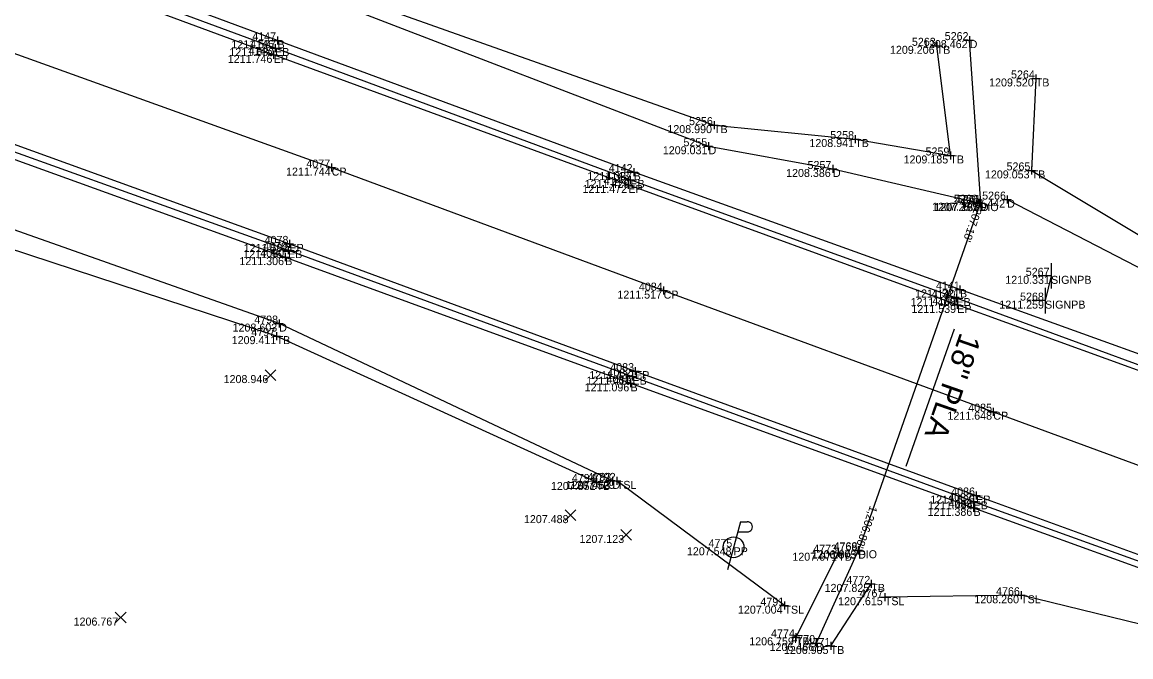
# Model space of a CAD drawing. Extents: x 2044996 to 2050343, y 455232 to 458054.
# Drawn here: x 2048212.4 to 2048351, y 456708.6 to 456787.9 of the extents above; entities that cross this region are included whole.
import ezdxf

# ---------------------------------------------------------------- set-up
doc = ezdxf.new("R2010")
doc.units = 0
for name, color, linetype in [('Default', 7, 'Continuous'), ('DR_X_Ditch', 7, 'Continuous'), ('DR_X_Elev_Flow', 7, 'Continuous'), ('DR_X_Storm_Sewer', 7, 'Continuous'), ('DR_X_Text', 7, 'Continuous'), ('DT_X_Contour_Minor', 7, 'Continuous'), ('DT_X_Contour_Text', 7, 'Continuous'), ('DT_X_Spot_Elev', 7, 'Continuous'), ('DT_X_Triangles', 7, 'Continuous'), ('DT_X_Void', 7, 'Continuous'), ('PV_X_COP', 7, 'Continuous'), ('PV_X_EOP', 7, 'Continuous'), ('PV_X_Shoulder_Aggregate', 7, 'Continuous'), ('SC_Scratch1', 7, 'Continuous'), ('SN_X_Public', 7, 'Continuous'), ('SV_X_Break_Lines', 7, 'Continuous'), ('SV_X_Toe_of_Slope', 7, 'Continuous'), ('SV_X_Top_of_Bank', 7, 'Continuous'), ('UT_X_Electric_Cells', 7, 'Continuous')]:
    doc.layers.add(name, color=color, linetype=linetype)

msp = doc.modelspace()

# ---------------------------------------------------------------- linework, layer by layer
at = {"layer": 'Default'}
msp.add_lwpolyline([(2048341.03, 456756.21), (2048340.28, 456753.11)], dxfattribs=at)
at = {"layer": 'DR_X_Ditch'}
for points in [[(2047780.51, 456960.13), (2047826.93, 456942.06), (2047870.38, 456926.94), (2047917.77, 456909.91), (2047942.94, 456900.89), (2047986.92, 456884.17), (2048032.77, 456867.49), (2048075.71, 456852.37), (2048118.48, 456836.63), (2048162.27, 456821), (2048204.38, 456806.34), (2048252.02, 456790.17), (2048298.22, 456772.41), (2048313.77, 456769.57), (2048332, 456765.35)], [(2048286.21, 456730.57), (2048244.57, 456750.24), (2048196.78, 456767.13), (2048157.76, 456781.54), (2048113.45, 456797.91), (2048070.52, 456814.66)], [(2048332.26, 456765.31), (2048330.86, 456785.68)], [(2048335.55, 456765.74), (2048373.99, 456745.88), (2048418.01, 456728.27), (2048467.59, 456710.52), (2048510.97, 456693.84), (2048561.78, 456674.87), (2048608.72, 456657.51)], [(2048316.94, 456721.85), (2048311.69, 456710.3)]]:
    msp.add_lwpolyline(points, dxfattribs=at)
at = {"layer": 'DR_X_Elev_Flow'}
for p, q in [((2048331.68, 456765.3), (2048332.68, 456765.3)), ((2048332.18, 456765.8), (2048332.18, 456764.8)), ((2048332.18, 456765.3), (2048332.18, 456765.3)), ((2048316.48, 456721.9), (2048317.48, 456721.9)), ((2048316.98, 456722.4), (2048316.98, 456721.4)), ((2048316.98, 456721.9), (2048316.98, 456721.9))]:
    msp.add_line(p, q, dxfattribs=at)
at = {"layer": 'DR_X_Storm_Sewer'}
msp.add_line((2048332.18, 456765.3), (2048316.98, 456721.9), dxfattribs=at)
at = {"layer": 'DR_X_Text'}
msp.add_line((2048322.94, 456732.4), (2048328.96, 456749.6), dxfattribs=at)
at = {"layer": 'DT_X_Spot_Elev'}
for p, q in [((2048242.8, 456743.14), (2048244.13, 456744.47)), ((2048242.8, 456744.47), (2048244.13, 456743.14)), ((2048280.32, 456725.62), (2048281.65, 456726.95)), ((2048280.32, 456726.95), (2048281.65, 456725.62)), ((2048287.26, 456723.15), (2048288.59, 456724.48)), ((2048287.26, 456724.48), (2048288.59, 456723.15)), ((2048224.08, 456712.82), (2048225.42, 456714.15)), ((2048224.08, 456714.15), (2048225.42, 456712.82))]:
    msp.add_line(p, q, dxfattribs=at)
at = {"layer": 'DT_X_Void'}
for p, q in [((2048243.86, 456785.65), (2048244.86, 456785.65)), ((2048244.36, 456786.15), (2048244.36, 456785.15)), ((2048244.36, 456785.65), (2048244.36, 456785.65)), ((2048330.36, 456785.68), (2048331.36, 456785.68)), ((2048330.86, 456786.18), (2048330.86, 456785.18)), ((2048330.86, 456785.68), (2048330.86, 456785.68)), ((2048243.56, 456784.69), (2048244.56, 456784.69)), ((2048243.87, 456784.34), (2048243.87, 456783.34)), ((2048244.06, 456785.19), (2048244.06, 456784.19)), ((2048244.06, 456784.69), (2048244.06, 456784.69)), ((2048326.24, 456784.97), (2048327.24, 456784.97)), ((2048326.74, 456785.47), (2048326.74, 456784.47)), ((2048326.74, 456784.97), (2048326.74, 456784.97)), ((2048243.37, 456783.84), (2048244.37, 456783.84)), ((2048243.87, 456783.84), (2048243.87, 456783.84)), ((2048338.62, 456780.89), (2048339.62, 456780.89)), ((2048339.12, 456781.39), (2048339.12, 456780.39)), ((2048339.12, 456780.89), (2048339.12, 456780.89)), ((2048298.41, 456775.05), (2048299.41, 456775.05)), ((2048298.91, 456775.55), (2048298.91, 456774.55)), ((2048298.91, 456775.05), (2048298.91, 456775.05)), ((2048316.05, 456773.31), (2048317.05, 456773.31)), ((2048316.55, 456773.81), (2048316.55, 456772.81)), ((2048316.55, 456773.31), (2048316.55, 456773.31)), ((2048297.72, 456772.41), (2048298.72, 456772.41)), ((2048298.22, 456772.91), (2048298.22, 456771.91)), ((2048298.22, 456772.41), (2048298.22, 456772.41)), ((2048328.45, 456771.76), (2048328.45, 456770.76)), ((2048327.95, 456771.26), (2048328.95, 456771.26)), ((2048328.45, 456771.26), (2048328.45, 456771.26)), ((2048250.62, 456769.74), (2048251.62, 456769.74)), ((2048251.12, 456770.24), (2048251.12, 456769.24)), ((2048251.12, 456769.74), (2048251.12, 456769.74)), ((2048288.37, 456769.18), (2048289.37, 456769.18)), ((2048288.87, 456769.68), (2048288.87, 456768.68)), ((2048288.87, 456769.18), (2048288.87, 456769.18)), ((2048313.27, 456769.57), (2048314.27, 456769.57)), ((2048313.77, 456770.07), (2048313.77, 456769.07)), ((2048313.77, 456769.57), (2048313.77, 456769.57)), ((2048338.1, 456769.39), (2048339.1, 456769.39)), ((2048338.6, 456769.89), (2048338.6, 456768.89)), ((2048338.6, 456769.39), (2048338.6, 456769.39)), ((2048287.7, 456767.58), (2048288.7, 456767.58)), ((2048287.95, 456768.21), (2048288.95, 456768.21)), ((2048288.2, 456768.08), (2048288.2, 456767.08)), ((2048288.2, 456767.58), (2048288.2, 456767.58)), ((2048288.45, 456768.71), (2048288.45, 456767.71)), ((2048288.45, 456768.21), (2048288.45, 456768.21)), ((2048335.55, 456766.24), (2048335.55, 456765.24)), ((2048331.5, 456765.35), (2048332.5, 456765.35)), ((2048331.76, 456765.31), (2048332.76, 456765.31)), ((2048332, 456765.85), (2048332, 456764.85)), ((2048332, 456765.35), (2048332, 456765.35)), ((2048332.26, 456765.81), (2048332.26, 456764.81)), ((2048332.26, 456765.31), (2048332.26, 456765.31)), ((2048335.05, 456765.74), (2048336.05, 456765.74)), ((2048335.55, 456765.74), (2048335.55, 456765.74)), ((2048245.85, 456760.7), (2048245.85, 456759.7)), ((2048245.17, 456759.42), (2048246.17, 456759.42)), ((2048245.35, 456760.2), (2048246.35, 456760.2)), ((2048245.67, 456759.92), (2048245.67, 456758.92)), ((2048245.67, 456759.42), (2048245.67, 456759.42)), ((2048245.85, 456760.2), (2048245.85, 456760.2)), ((2048244.82, 456758.55), (2048245.82, 456758.55)), ((2048245.32, 456759.05), (2048245.32, 456758.05)), ((2048245.32, 456758.55), (2048245.32, 456758.55)), ((2048292.11, 456754.36), (2048293.11, 456754.36)), ((2048292.61, 456754.86), (2048292.61, 456753.86)), ((2048292.61, 456754.36), (2048292.61, 456754.36)), ((2048329.15, 456754.5), (2048330.15, 456754.5)), ((2048329.21, 456753.93), (2048329.21, 456752.93)), ((2048329.65, 456755), (2048329.65, 456754)), ((2048329.65, 456754.5), (2048329.65, 456754.5)), ((2048328.71, 456753.43), (2048329.71, 456753.43)), ((2048328.8, 456752.57), (2048329.8, 456752.57)), ((2048329.21, 456753.43), (2048329.21, 456753.43)), ((2048329.3, 456753.07), (2048329.3, 456752.07)), ((2048329.3, 456752.57), (2048329.3, 456752.57)), ((2048244.07, 456750.24), (2048245.07, 456750.24)), ((2048244.57, 456750.74), (2048244.57, 456749.74)), ((2048244.57, 456750.24), (2048244.57, 456750.24)), ((2048243.74, 456748.67), (2048244.74, 456748.67)), ((2048244.24, 456749.17), (2048244.24, 456748.17)), ((2048244.24, 456748.67), (2048244.24, 456748.67)), ((2048288.55, 456744.29), (2048289.55, 456744.29)), ((2048288.72, 456744.11), (2048288.72, 456743.11)), ((2048289.05, 456744.79), (2048289.05, 456743.79)), ((2048289.05, 456744.29), (2048289.05, 456744.29)), ((2048287.98, 456742.77), (2048288.98, 456742.77)), ((2048288.22, 456743.61), (2048289.22, 456743.61)), ((2048288.48, 456743.27), (2048288.48, 456742.27)), ((2048288.48, 456742.77), (2048288.48, 456742.77)), ((2048288.72, 456743.61), (2048288.72, 456743.61)), ((2048333.31, 456739.22), (2048334.31, 456739.22)), ((2048333.81, 456739.72), (2048333.81, 456738.72)), ((2048333.81, 456739.22), (2048333.81, 456739.22)), ((2048283.73, 456730.43), (2048284.73, 456730.43)), ((2048284.23, 456730.93), (2048284.23, 456729.93)), ((2048284.23, 456730.43), (2048284.23, 456730.43)), ((2048285.71, 456730.57), (2048286.71, 456730.57)), ((2048286.21, 456731.07), (2048286.21, 456730.07)), ((2048286.21, 456730.57), (2048286.21, 456730.57)), ((2048286.26, 456730.57), (2048287.26, 456730.57)), ((2048286.76, 456731.07), (2048286.76, 456730.07)), ((2048286.76, 456730.57), (2048286.76, 456730.57)), ((2048331.67, 456729.24), (2048331.67, 456728.24)), ((2048330.85, 456728.01), (2048331.85, 456728.01)), ((2048331.17, 456728.74), (2048332.17, 456728.74)), ((2048331.35, 456728.51), (2048331.35, 456727.51)), ((2048331.35, 456728.01), (2048331.35, 456728.01)), ((2048331.35, 456727.7), (2048331.35, 456726.7)), ((2048331.67, 456728.74), (2048331.67, 456728.74)), ((2048330.85, 456727.2), (2048331.85, 456727.2)), ((2048331.35, 456727.2), (2048331.35, 456727.2)), ((2048314.42, 456722.09), (2048314.42, 456721.09)), ((2048316.44, 456721.85), (2048317.44, 456721.85)), ((2048316.94, 456722.35), (2048316.94, 456721.35)), ((2048316.94, 456721.85), (2048316.94, 456721.85)), ((2048313.92, 456721.59), (2048314.92, 456721.59)), ((2048314.42, 456721.59), (2048314.42, 456721.59)), ((2048318.57, 456718.19), (2048318.57, 456717.19)), ((2048318.07, 456717.69), (2048319.07, 456717.69)), ((2048318.57, 456717.69), (2048318.57, 456717.69)), ((2048320.26, 456716.53), (2048320.26, 456715.53)), ((2048337.28, 456716.77), (2048337.28, 456715.77)), ((2048307.21, 456714.97), (2048308.21, 456714.97)), ((2048307.71, 456715.47), (2048307.71, 456714.47)), ((2048307.71, 456714.97), (2048307.71, 456714.97)), ((2048319.76, 456716.03), (2048320.76, 456716.03)), ((2048320.26, 456716.03), (2048320.26, 456716.03)), ((2048336.78, 456716.27), (2048337.78, 456716.27)), ((2048337.28, 456716.27), (2048337.28, 456716.27)), ((2048308.63, 456711.01), (2048309.63, 456711.01)), ((2048309.13, 456711.51), (2048309.13, 456710.51)), ((2048309.13, 456711.01), (2048309.13, 456711.01)), ((2048311.69, 456710.8), (2048311.69, 456709.8)), ((2048311.19, 456710.3), (2048312.19, 456710.3)), ((2048311.69, 456710.3), (2048311.69, 456710.3)), ((2048312.99, 456709.93), (2048313.99, 456709.93)), ((2048313.49, 456710.43), (2048313.49, 456709.43)), ((2048313.49, 456709.93), (2048313.49, 456709.93))]:
    msp.add_line(p, q, dxfattribs=at)
at = {"layer": 'PV_X_COP'}
msp.add_lwpolyline([(2047721.58, 456961.45), (2047764.11, 456945.53), (2047805.42, 456930.56), (2047848.07, 456915.19), (2047886.38, 456901.23), (2047928.53, 456886.16), (2047967.24, 456872.35), (2048004.2, 456859.18), (2048043.3, 456845.25), (2048086.02, 456829.64), (2048125.99, 456815.39), (2048168.62, 456799.78), (2048207.67, 456785.38), (2048251.12, 456769.74), (2048292.61, 456754.36), (2048333.81, 456739.22), (2048373.81, 456724.48), (2048417.09, 456709.08), (2048458.61, 456693.82), (2048498.86, 456678.79), (2048537.43, 456664.8), (2048579.13, 456649.5), (2048615.78, 456636.27)], dxfattribs=at)
at = {"layer": 'PV_X_EOP'}
for p, q in [((2048243.87, 456783.84), (2048200.13, 456800.03)), ((2048288.2, 456767.58), (2048243.87, 456783.84)), ((2048203.99, 456775.35), (2048245.85, 456760.2)), ((2048329.3, 456752.57), (2048288.2, 456767.58)), ((2048245.85, 456760.2), (2048289.05, 456744.29)), ((2048369.11, 456738.16), (2048329.3, 456752.57)), ((2048289.05, 456744.29), (2048331.67, 456728.74)), ((2048331.67, 456728.74), (2048371.07, 456714.38))]:
    msp.add_line(p, q, dxfattribs=at)
at = {"layer": 'PV_X_Shoulder_Aggregate'}
for points in [[(2048620.54, 456647.12), (2048583.12, 456660.67), (2048539.73, 456676.45), (2048498.23, 456691.52), (2048454.17, 456707.97), (2048410.24, 456724.1), (2048369.4, 456738.65), (2048329.21, 456753.43), (2048288.45, 456768.21), (2048244.06, 456784.69), (2048200.54, 456800.78), (2048154.81, 456817.47), (2048112.55, 456832.71), (2048067.31, 456849.18), (2048026.51, 456863.76), (2047982.25, 456879.67), (2047938.09, 456895.41), (2047894.6, 456910.89), (2047855.83, 456924.74), (2047813.34, 456939.9), (2047765.41, 456957.6), (2047718.77, 456974.89)], [(2048040.39, 456833.65), (2048080.57, 456819.36), (2048122.88, 456804.21), (2048163.75, 456789.21), (2048203.9, 456774.44), (2048245.67, 456759.42), (2048288.72, 456743.61), (2048331.35, 456728.01), (2048370.94, 456713.7), (2048413.11, 456698.36), (2048454.57, 456682.93), (2048494.04, 456668.41), (2048534.01, 456653.96), (2048574.84, 456639.09), (2048611.82, 456625.41)]]:
    msp.add_lwpolyline(points, dxfattribs=at)
at = {"layer": 'SN_X_Public'}
for p, q in [((2048341.03, 456757.81), (2048341.03, 456754.61)), ((2048341.03, 456756.21), (2048339.43, 456756.21)), ((2048340.28, 456754.71), (2048340.28, 456751.51)), ((2048340.28, 456753.11), (2048338.68, 456753.11))]:
    msp.add_line(p, q, dxfattribs=at)
at = {"layer": 'SV_X_Break_Lines'}
for points in [[(2048620.73, 456648.35), (2048583.39, 456661.98), (2048539.9, 456677.65), (2048498.37, 456692.73), (2048454.2, 456708.99), (2048410.48, 456724.96), (2048370.07, 456739.9), (2048329.65, 456754.5), (2048288.87, 456769.18), (2048244.36, 456785.65), (2048200.73, 456801.81), (2048154.72, 456818.61), (2048112.67, 456833.97), (2048067.63, 456850.21), (2048026.62, 456865.12), (2047982.64, 456881.49), (2047938.6, 456897.69), (2047895.04, 456913.55), (2047856.96, 456927.13), (2047813.61, 456942.44), (2047766.63, 456959.74), (2047718.99, 456976.33)], [(2047983.65, 456851.86), (2047998.98, 456847.09), (2048040.01, 456832.79), (2048080.02, 456818.41), (2048122.45, 456803.47), (2048163.47, 456788.33), (2048203.54, 456773.63), (2048245.32, 456758.55), (2048288.48, 456742.77), (2048331.35, 456727.2), (2048370.69, 456712.96), (2048412.95, 456697.59), (2048454.31, 456682.22), (2048493.85, 456667.9), (2048533.48, 456653.1), (2048574.57, 456638.27), (2048611.5, 456624.45)]]:
    msp.add_lwpolyline(points, dxfattribs=at)
at = {"layer": 'SV_X_Toe_of_Slope'}
for points in [[(2048307.71, 456714.97), (2048286.76, 456730.57)], [(2048404.84, 456696.78), (2048369.02, 456708.55), (2048337.28, 456716.27), (2048320.26, 456716.03)]]:
    msp.add_lwpolyline(points, dxfattribs=at)
at = {"layer": 'SV_X_Top_of_Bank'}
for points in [[(2047763.11, 456969.57), (2047782.88, 456962.79), (2047830.39, 456947.65), (2047873.41, 456931.98), (2047921.78, 456915.49), (2047944.39, 456907.04), (2047986.44, 456890.77), (2048035.77, 456871.04), (2048076.02, 456855.86), (2048121.82, 456840.13), (2048161.94, 456823.83), (2048204.58, 456808.51), (2048251.96, 456791.72), (2048298.91, 456775.05), (2048316.55, 456773.31), (2048328.45, 456771.26), (2048326.74, 456784.97)], [(2048284.23, 456730.43), (2048244.24, 456748.67), (2048196.38, 456764.37), (2048156.4, 456780.03), (2048112.39, 456796.2), (2048069.57, 456813.69)], [(2048339.12, 456780.89), (2048338.6, 456769.39), (2048375.24, 456747.38), (2048425.64, 456735.22), (2048467.88, 456719.52), (2048517.9, 456700.47), (2048561.92, 456683.71), (2048612.49, 456664.63)], [(2048314.42, 456721.59), (2048309.13, 456711.01)], [(2048313.49, 456709.93), (2048318.57, 456717.69)]]:
    msp.add_lwpolyline(points, dxfattribs=at)
at = {"layer": 'UT_X_Electric_Cells'}
for p, q in [((2048302.21, 456725.47), (2048300.6, 456719.47)), ((2048302.21, 456725.47), (2048303.06, 456725.47)), ((2048301.87, 456724.2), (2048303.06, 456724.2))]:
    msp.add_line(p, q, dxfattribs=at)
msp.add_circle((2048301.35, 456722.27), 1.3, dxfattribs=at)
msp.add_arc((2048303.07, 456724.83), 0.638, 268.8767, 91.1233, dxfattribs=at)

# ---------------------------------------------------------------- texts
at = {"layer": 'DR_X_Text'}
msp.add_text('18" PLA', height=2.8, rotation=250.7068, dxfattribs=at).set_placement((2048329.7, 456749.23))
at = {"layer": 'DT_X_Contour_Minor'}
for s, p in [('1211.577', (2048238.58, 456784.65)), ('1208.462', (2048325.02, 456784.68)), ('1211.680', (2048238.33, 456783.69)), ('1209.206', (2048320.9, 456783.97)), ('1211.746', (2048238.14, 456782.84)), ('1209.520', (2048333.29, 456779.89)), ('1208.990', (2048293.08, 456774.05)), ('1208.941', (2048310.83, 456772.31)), ('1209.031', (2048292.51, 456771.41)), ('1209.185', (2048322.6, 456770.26)), ('1211.744', (2048245.42, 456768.74)), ('1211.337', (2048283.09, 456768.18)), ('1208.386', (2048307.92, 456768.57)), ('1209.053', (2048332.77, 456768.39)), ('1211.472', (2048282.47, 456766.58)), ('1211.429', (2048282.74, 456767.21)), ('1207.250', (2048326.16, 456764.35)), ('1207.285', (2048326.41, 456764.31)), ('1207.181', (2048326.46, 456764.3)), ('1207.442', (2048329.71, 456764.74)), ('1211.561', (2048240.06, 456758.42)), ('1211.592', (2048240.13, 456759.2)), ('1211.306', (2048239.59, 456757.55)), ('1210.331', (2048335.31, 456755.21)), ('1211.517', (2048286.83, 456753.36)), ('1211.321', (2048324.04, 456753.5)), ('1211.460', (2048323.48, 456752.43)), ('1211.539', (2048323.58, 456751.57)), ('1211.259', (2048334.57, 456752.11)), ('1208.603', (2048238.74, 456749.24)), ('1209.411', (2048238.63, 456747.67)), ('1211.432', (2048283.32, 456743.29)), ('1208.946', (2048237.62, 456742.8)), ('1211.096', (2048282.74, 456741.77)), ('1211.415', (2048282.97, 456742.61)), ('1211.648', (2048328.08, 456738.22)), ('1207.851', (2048278.52, 456729.43)), ('1207.463', (2048280.38, 456729.57)), ('1207.529', (2048280.94, 456729.57)), ('1211.494', (2048325.65, 456727.01)), ('1211.526', (2048325.93, 456727.74)), ('1207.488', (2048275.15, 456725.29)), ('1211.386', (2048325.61, 456726.2)), ('1207.123', (2048282.1, 456722.81)), ('1207.548', (2048295.52, 456721.27)), ('1206.903', (2048311.11, 456720.85)), ('1206.875', (2048311.13, 456720.9)), ('1207.671', (2048308.7, 456720.59)), ('1207.825', (2048312.73, 456716.69)), ('1207.004', (2048301.9, 456713.97)), ('1207.615', (2048314.42, 456715.03)), ('1208.260', (2048331.45, 456715.27)), ('1206.767', (2048218.87, 456712.48)), ('1206.759', (2048303.31, 456710.01)), ('1206.466', (2048305.85, 456709.3)), ('1206.905', (2048307.64, 456708.93))]:
    msp.add_text(s, height=1, dxfattribs=at).set_placement(p)
at = {"layer": 'DT_X_Contour_Text'}
for s, p in [('B', (2048244.36, 456784.65)), ('D', (2048330.86, 456784.68)), ('EB', (2048244.06, 456783.69)), ('TB', (2048326.74, 456783.97)), ('EP', (2048243.87, 456782.84)), ('TB', (2048339.12, 456779.89)), ('TB', (2048298.91, 456774.05)), ('TB', (2048316.55, 456772.31)), ('D', (2048298.22, 456771.41)), ('TB', (2048328.45, 456770.26)), ('CP', (2048251.12, 456768.74)), ('B', (2048288.87, 456768.18)), ('D', (2048313.77, 456768.57)), ('TB', (2048338.6, 456768.39)), ('EP', (2048288.2, 456766.58)), ('EB', (2048288.45, 456767.21)), ('D', (2048332, 456764.35)), ('PIO', (2048332.18, 456764.3)), ('D', (2048332.26, 456764.31)), ('D', (2048335.55, 456764.74)), ('EB', (2048245.67, 456758.42)), ('EP', (2048245.85, 456759.2)), ('B', (2048245.32, 456757.55)), ('SIGNPB', (2048341.03, 456755.21)), ('CP', (2048292.61, 456753.36)), ('B', (2048329.65, 456753.5)), ('EB', (2048329.21, 456752.43)), ('EP', (2048329.3, 456751.57)), ('SIGNPB', (2048340.28, 456752.11)), ('D', (2048244.57, 456749.24)), ('TB', (2048244.24, 456747.67)), ('EP', (2048289.05, 456743.29)), ('B', (2048288.48, 456741.77)), ('EB', (2048288.72, 456742.61)), ('CP', (2048333.81, 456738.22)), ('TB', (2048284.23, 456729.43)), ('D', (2048286.21, 456729.57)), ('TSL', (2048286.76, 456729.57)), ('EB', (2048331.35, 456727.01)), ('EP', (2048331.67, 456727.74)), ('B', (2048331.35, 456726.2)), ('PP', (2048301.35, 456721.27)), ('D', (2048316.94, 456720.85)), ('PIO', (2048316.98, 456720.9)), ('TB', (2048314.42, 456720.59)), ('TB', (2048318.57, 456716.69)), ('TSL', (2048307.71, 456713.97)), ('TSL', (2048320.26, 456715.03)), ('TSL', (2048337.28, 456715.27)), ('TB', (2048309.13, 456710.01)), ('D', (2048311.69, 456709.3)), ('TB', (2048313.49, 456708.93))]:
    msp.add_text(s, height=1, dxfattribs=at).set_placement(p)
at = {"layer": 'DT_X_Triangles'}
for s, p in [('4146', (2048240.94, 456784.69)), ('4147', (2048241.2, 456785.65)), ('5263', (2048323.64, 456784.97)), ('5262', (2048327.74, 456785.68)), ('4145', (2048240.74, 456783.84)), ('5264', (2048336.03, 456780.89)), ('5256', (2048295.79, 456775.05)), ('5255', (2048295.09, 456772.41)), ('5258', (2048313.43, 456773.31)), ('5259', (2048325.35, 456771.26)), ('4077', (2048247.96, 456769.74)), ('5257', (2048310.6, 456769.57)), ('5265', (2048335.47, 456769.39)), ('4143', (2048285.34, 456768.21)), ('4142', (2048285.75, 456769.18)), ('4144', (2048285.11, 456767.58)), ('5260', (2048328.88, 456765.35)), ('4776', (2048329.05, 456765.3)), ('5261', (2048329.26, 456765.31)), ('5266', (2048332.42, 456765.74)), ('4078', (2048242.74, 456760.2)), ('4080', (2048242.2, 456758.55)), ('4079', (2048242.57, 456759.42)), ('5267', (2048337.87, 456756.21)), ('4084', (2048289.52, 456754.36)), ('4141', (2048326.65, 456754.5)), ('4140', (2048326.09, 456753.43)), ('5268', (2048337.16, 456753.11)), ('4139', (2048326.2, 456752.57)), ('4798', (2048241.45, 456750.24)), ('4797', (2048241.08, 456748.67)), ('4082', (2048285.6, 456743.61)), ('4083', (2048285.94, 456744.29)), ('4081', (2048285.48, 456742.77)), ('4085', (2048330.68, 456739.22)), ('4793', (2048283.1, 456730.57)), ('4792', (2048283.64, 456730.57)), ('4794', (2048281.14, 456730.43)), ('4087', (2048328.19, 456728.01)), ('4086', (2048328.55, 456728.74)), ('4088', (2048328.23, 456727.2)), ('4775', (2048298.22, 456722.27)), ('4773', (2048311.31, 456721.59)), ('4769', (2048313.84, 456721.85)), ('4768', (2048313.86, 456721.9)), ('4772', (2048315.46, 456717.69)), ('4767', (2048317.1, 456716.03)), ('4766', (2048334.16, 456716.27)), ('4791', (2048304.71, 456714.97)), ('4774', (2048306.04, 456711.01)), ('4770', (2048308.57, 456710.3)), ('4771', (2048310.49, 456709.93))]:
    msp.add_text(s, height=1, dxfattribs=at).set_placement(p)
at = {"layer": 'SC_Scratch1'}
for s, p in [("1207.18'", (2048331.7, 456765.47)), ("1,206.88'", (2048318.42, 456727.53))]:
    msp.add_text(s, height=1, rotation=250.7068, dxfattribs=at).set_placement(p)

doc.saveas('drawing.dxf')
